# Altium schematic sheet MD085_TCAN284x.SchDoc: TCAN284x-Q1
size 431 x 279 mm; Date: Not shown in title block; ApprovedBy: Not shown in title block; CheckedBy: Not shown in title block; Author: Not shown in title block; CompanyName: Not shown in title block; DrawnBy: Keerthi Kumanan; Engineer: Not shown in title block; Organization: Not shown in title block; Address1: Not shown in title block; Address2: Not shown in title block; Address3: Not shown in title block; Address4: Not shown in title block; DocumentNumber: 1; Revision: Use project parameter SCH_Rev; SheetNumber: 5; SheetTotal: 1; PageSetup: Record=PageOptions¦CenterHorizontal=True¦CenterVertical=True¦PrintScale=1.00¦XCorrection=1.00¦YCorrection=1.00¦PrintKind=0¦BorderSize=5000000¦LeftOffset=0¦BottomOffset=0¦Orientation=2¦PaperLength=1000¦PaperWidth=1000¦Scale=100¦PaperSource=15¦PrintQuality=600¦MediaType=1¦DitherType=10¦PaperKind=Letter¦PrintScaleMode=1
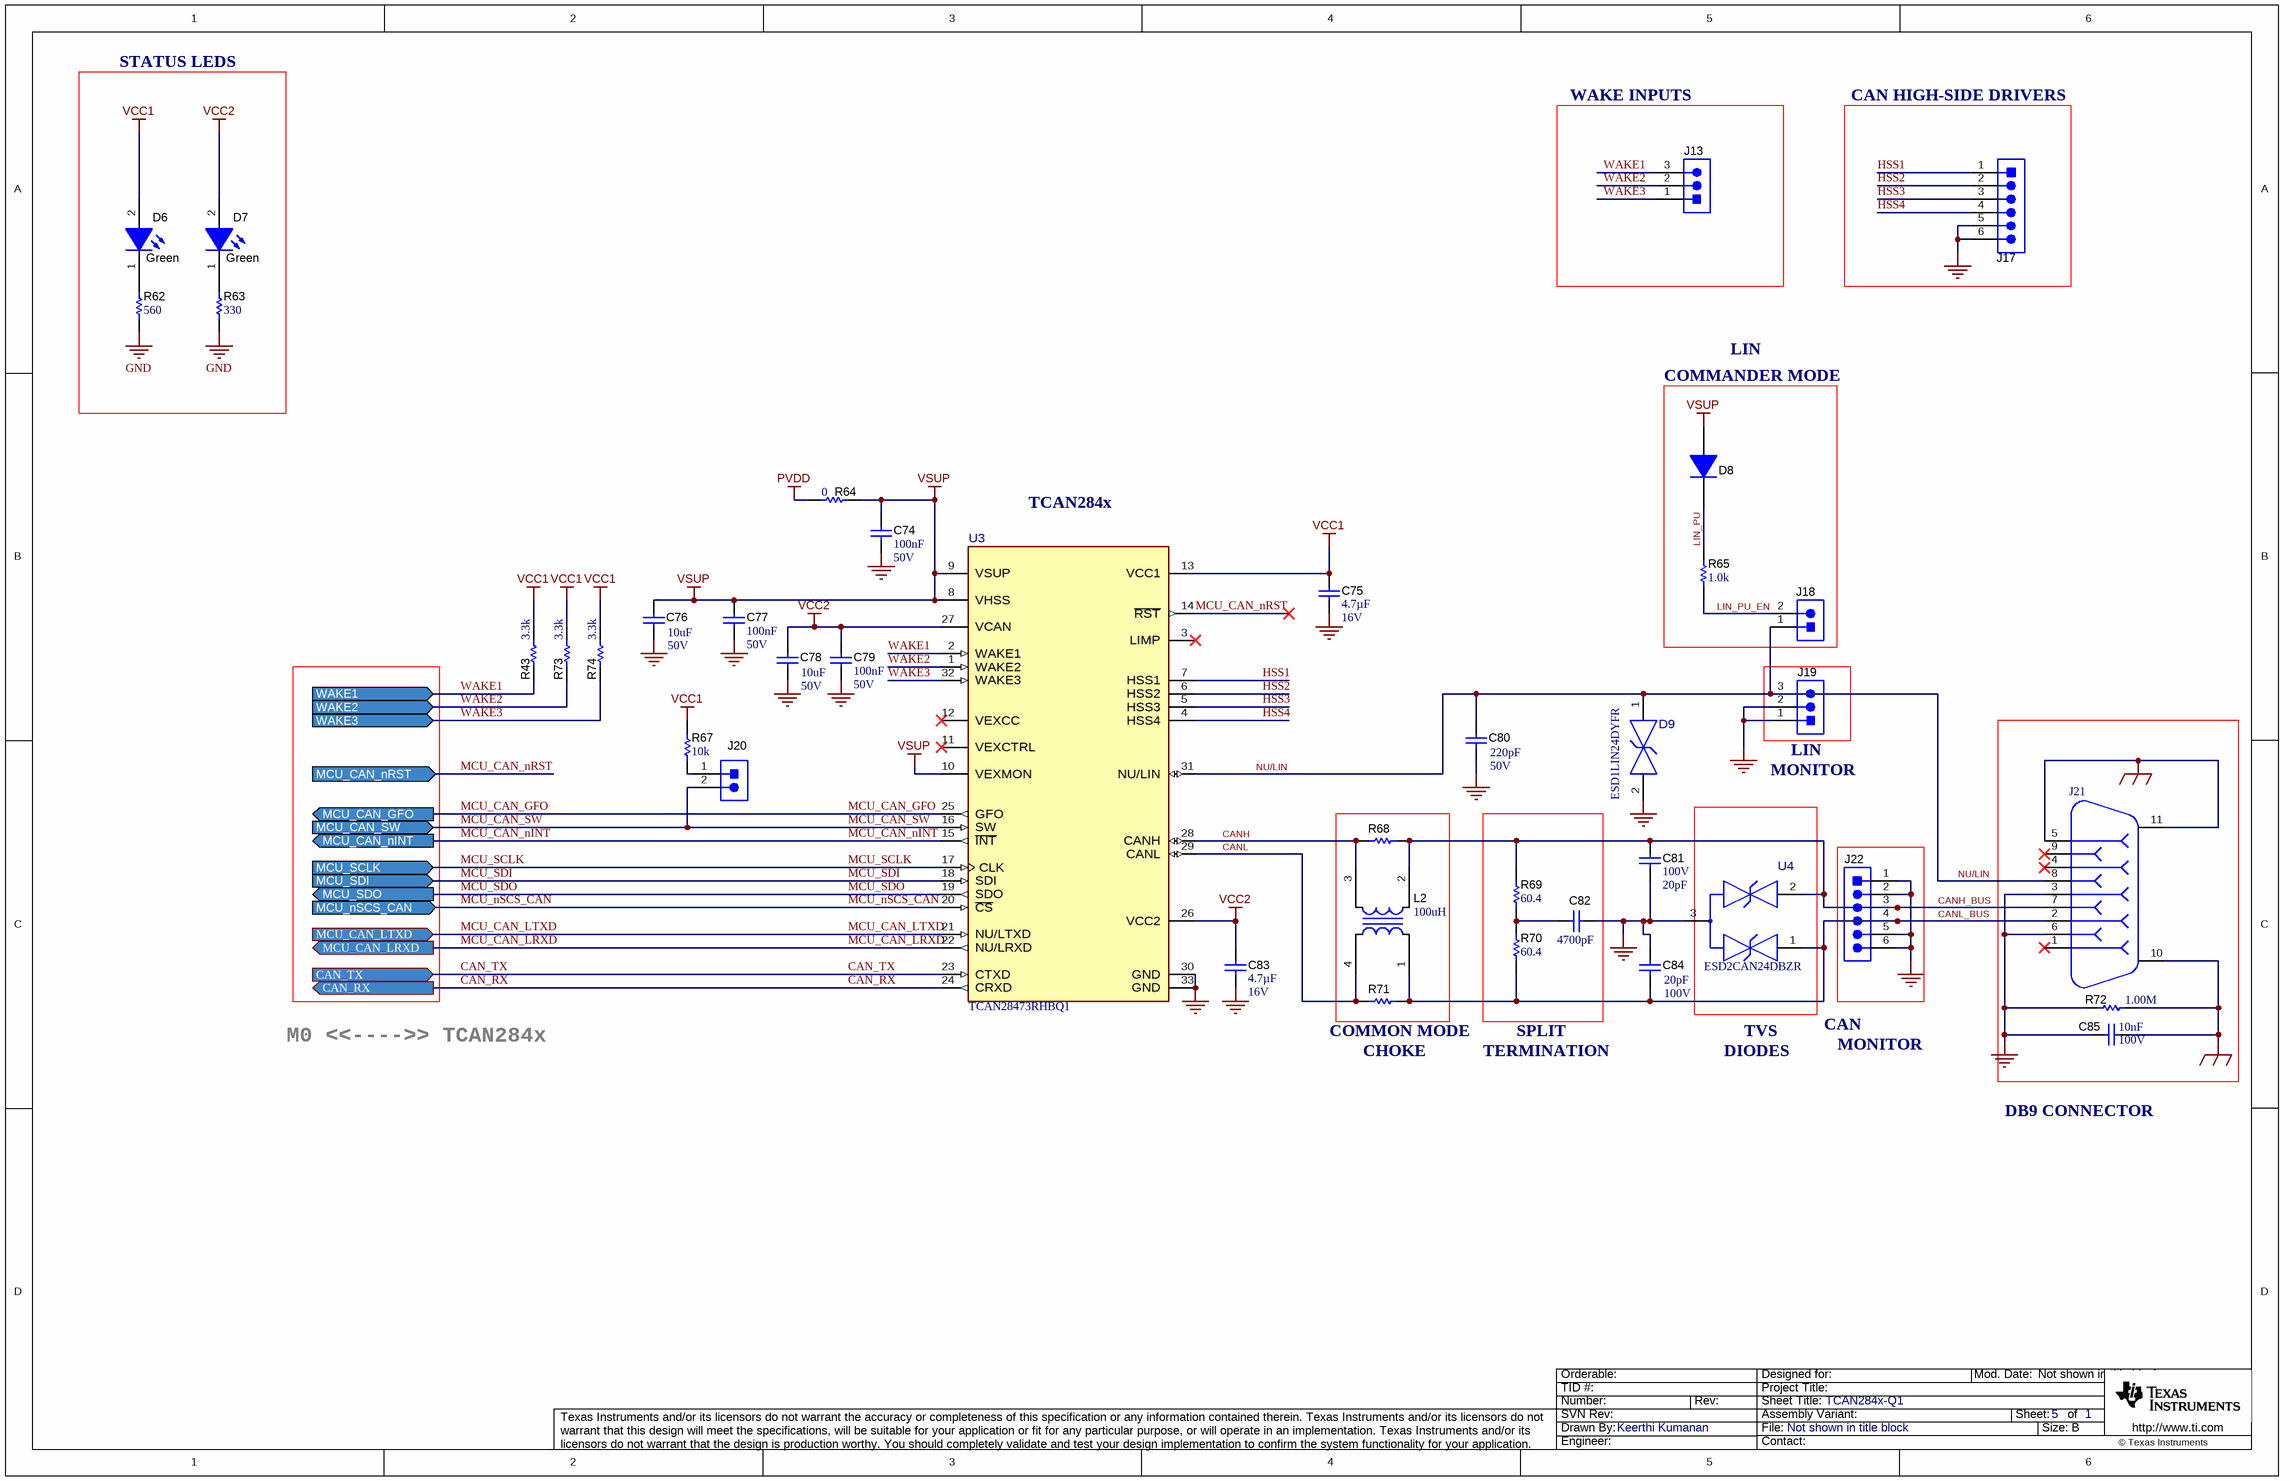
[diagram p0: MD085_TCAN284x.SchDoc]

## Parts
C74  Cap_F: 100nF  VDC_V: 50V  [0603S]  (hidden comment: C1608X7R1H104K080AA)
C75  Cap_F: 4.7µF  VDC_V: 16V  [0805L]  (hidden comment: CGA4J3X7R1C475K125AE)
C76  VDC_V: 50V  ValueDisplayed: 10uF  [1206_180]  (hidden comment: CL31B106KBHNNNE)
C77  Cap_F: 100nF  VDC_V: 50V  [0603S]  (hidden comment: C1608X7R1H104K080AA)
C78  VDC_V: 50V  ValueDisplayed: 10uF  [1206_180]  (hidden comment: CL31B106KBHNNNE)
C79  Cap_F: 100nF  VDC_V: 50V  [0603S]  (hidden comment: C1608X7R1H104K080AA)
C80  Value2: 50V  ValueDisplayed: 220pF  [0603S]  (hidden comment: 06035A221FAT2A)
C81  VDC_V: 100V  ValueDisplayed: 20pF  [0603S]  (hidden comment: GRM1885C2A200JA01D)
C82  ValueDisplayed: 4700pF  [0603S]  (hidden comment: 06031C472KAT2A)
C83  Cap_F: 4.7µF  VDC_V: 16V  [0805L]  (hidden comment: CGA4J3X7R1C475K125AE)
C84  VDC_V: 100V  ValueDisplayed: 20pF  [0603S]  (hidden comment: GRM1885C2A200JA01D)
C85  Cap_F: 10nF  VDC_V: 100V  [0603S]  (hidden comment: C0603X103K1RACTU)
D6  value Green  [WL-SMCW_GREEN]  (hidden comment: 150060VS75000)
D7  value Green  [WL-SMCW_GREEN]  (hidden comment: 150060VS75000)
D8  1N4148W-TP  [SOD-123]  (value not drawn)
D9  ESD1LIN24DYFR  [DYF0002A-MFG]
J13  TSW-103-07-G-S  [TSW-103-07-G-S]  (value not drawn)
J17  TSW-106-07-G-S  [TSW-106-07-G-S]  (value not drawn)
J18  TSW-102-07-G-S  [TSW-102-07-G-S]  (value not drawn)
J19  TSW-103-07-G-S  [TSW-103-07-G-S]  (value not drawn)
J20  TSW-102-07-G-S  [TSW-102-07-G-S]  (value not drawn)
J21  190-009-263R001  [NORCOMP_190-009-263R001]  (value not drawn)
J22  TSW-106-07-G-S  [TSW-106-07-G-S]  (value not drawn)
L2  ValueDisplayed: 100uH  [ACT45B_NoSilk]  (hidden comment: ACT45B-101-2P-TL003)
R43  ValueDisplayed: 3.3k  [0603]  (hidden comment: RC0603JR-073K3L)
R62  ValueDisplayed: 560  [0603]  (hidden comment: RC0603JR-07560RL)
R63  ValueDisplayed: 330  [0603]  (hidden comment: RC0603JR-07330RL)
R64  value 0  [0603]  (hidden comment: Resistor)
R65  ValueDisplayed: 1.0k  [0603]  (hidden comment: RC0603JR-071KL)
R67  ValueDisplayed: 10k  [0603]  (hidden comment: RC0603JR-0710KL)
R68  RC0603JR-070RL  [0603]  (value not drawn)
R69  ValueDisplayed: 60.4  [0603S]  (hidden comment: RC0603FR-0760R4L)
R70  ValueDisplayed: 60.4  [0603S]  (hidden comment: RC0603FR-0760R4L)
R71  RC0603JR-070RL  [0603]  (value not drawn)
R72  ValueDisplayed: 1.00M  [0402S]  (hidden comment: ERJ-2RKF1004X)
R73  ValueDisplayed: 3.3k  [0603]  (hidden comment: RC0603JR-073K3L)
R74  ValueDisplayed: 3.3k  [0603]  (hidden comment: RC0603JR-073K3L)
U3  TCAN28473RHBQ1  [RHB0032U-MFG]
U4  ESD2CAN24DBZR  [DBZ0003A-MFG]

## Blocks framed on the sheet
STATUS LEDS: D6 D7 R62 R63
WAKE INPUTS: J13
CAN HIGH-SIDE DRIVERS: J17
COMMANDER MODE: D8 J18 R65

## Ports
CAN_RX (out), CAN_TX (in), MCU_CAN_GFO (out), MCU_CAN_LRXD (out), MCU_CAN_LTXD (in), MCU_CAN_nINT (out), MCU_CAN_nRST (in), MCU_CAN_SW (in), MCU_nSCS_CAN (in), MCU_SCLK (in), MCU_SDI (in), MCU_SDO (out), WAKE1 (in), WAKE2 (in), WAKE3 (in)

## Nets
GND: C74.2 C75.2 C76.2 C77.2 C78.2 C79.2 C80.2 C81.2 C82.1 C83.2 C84.1 C85.2 D9.2(GND) J17.5 J17.6 J19.1 J19.2 J21.3 J21.6 J22.1 J22.2 J22.5 J22.6 R62.1 R63.1 R72.1 U3.30(GND) U3.33(GND) U4.3(GND)
PVDD: R64.2
SHIELD_GND: C85.1 J21.5 J21.10 J21.11 R72.2
VCC1: C75.1 D6.2(A) R43.2 R67.2 R73.2 R74.2 U3.13(VCC1)
VCC2: C78.1 C79.1 C83.1 D7.2(A) U3.26(VCC2) U3.27(VCAN)
VSUP: C74.1 C76.1 C77.1 D8.2(A) R64.1 U3.8(VHSS) U3.9(VSUP) U3.10(VEXMON)
CAN_RX: U3.24(CRXD) ; port CAN_RX
CAN_TX: U3.23(CTXD) ; port CAN_TX
CANH: L2.3 R68.1 U3.28(CANH)
CANH_BUS: C81.1 J21.7 J22.3 L2.2 R68.2 R69.2 U4.2(2_IO)
CANL: L2.4 R71.1 U3.29(CANL)
CANL_BUS: C84.2 J21.2 J22.4 L2.1 R70.1 R71.2 U4.1(1_IO)
HSS1: J17.1 U3.7(HSS1)
HSS2: J17.2 U3.6(HSS2)
HSS3: J17.3 U3.5(HSS3)
HSS4: J17.4 U3.4(HSS4)
LIN_PU: D8.1(K) R65.1
LIN_PU_EN: J18.2 R65.2
MCU_CAN_GFO: U3.25(GFO) ; port MCU_CAN_GFO
MCU_CAN_LRXD: U3.22(NU/LRXD) ; port MCU_CAN_LRXD
MCU_CAN_LTXD: U3.21(NU/LTXD) ; port MCU_CAN_LTXD
MCU_CAN_nINT: U3.15(~{INT}) ; port MCU_CAN_nINT
MCU_CAN_nRST: U3.14(~{RST}) ; port MCU_CAN_nRST
MCU_CAN_SW: J20.2 U3.16(SW) ; port MCU_CAN_SW
MCU_nSCS_CAN: U3.20(~{CS}) ; port MCU_nSCS_CAN
MCU_SCLK: U3.17(CLK) ; port MCU_SCLK
MCU_SDI: U3.18(SDI) ; port MCU_SDI
MCU_SDO: U3.19(SDO) ; port MCU_SDO
NU/LIN: C80.1 D9.1(IO) J18.1 J19.3 J21.8 U3.31(NU/LIN)
WAKE1: J13.3 R43.1 U3.2(WAKE1) ; port WAKE1
WAKE2: J13.2 R73.1 U3.1(WAKE2) ; port WAKE2
WAKE3: J13.1 R74.1 U3.32(WAKE3) ; port WAKE3
NetC82_2: C82.2 R69.1 R70.2
NetD6_1: D6.1(K) R62.2
NetD7_1: D7.1(K) R63.2
NetJ20_1: J20.1 R67.1

Not connected (* = marked no-connect by the designer): J21 1* 4* 9*; U3 3(LIMP)* 11(VEXCTRL)* 12(VEXCC)*

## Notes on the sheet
- LIN
- TCAN284x
- (near J19) LIN
- (near J19) MONITOR
- CAN
- M0 <<---->> TCAN284x
- (near R71) COMMON MODE
- (near R71) CHOKE
- TERMINATION
- SPLIT
- DIODES
- TVS
- MONITOR
- DB9 CONNECTOR

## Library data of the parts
C74 C77 C79 = CMP-0007044-5: CAP, CERM, 0.1 uF, 50 V, +/- 10%, X7R, 0603; Manufacturer: TDK; TaMin_C: -55°C; ESR_ohm: 29.6m; Polarized: N; SizeAreaWB_mm2: 4.68; Value1: 0.0296 ohm; U/M: EA; Value: 0.1uF; TaMax_C: 125°C; SizeZ_mm: 1; SizeX_mm: 1.6; SizeY_mm: 0.8; Cap_Case: 0603; SizeArea_mm2: 1.28; IRMS_A: 971.99mA; AEC Category: Q200
C75 C83 = CMP-0080701-1: CAP, CERM, 4.7 µF, 16 V,+/- 10%, X7R, AEC-Q200 Grade 1, 0805; Manufacturer: TDK; SizeAreaWB_mm2: 6.75; SizeArea_mm2: 2.5; AEC Qualified: Y; AEC Category: Q200; Value: 4.7uF; TaMax_C: 125°C; SizeZ_mm: 1.45; AEC Grade: 1; Polarized: N; TaMin_C: -55°C; SizeY_mm: 1.25; U/M: EA; SizeX_mm: 2; Cap_Case: 0805
C76 C78 = CMP-0008802-2: CAP, CERM, 10 uF, 50 V, +/- 10%, X7R, 1206; Manufacturer: Samsung; TaMin_C: -55°C; Polarized: N; SizeAreaWB_mm2: 10.92; Value1: Unknown; U/M: EA; Value: 10uF; TaMax_C: 125°C; SizeZ_mm: 1.8; SizeX_mm: 3.2; SizeY_mm: 1.6; Cap_Case: 1206; SizeArea_mm2: 5.12; Cap_F: 10µF; AEC Category: Q200
C80 = CMP-0006776-4: CAP, CERM, 220 pF, 50 V, +/- 1%, C0G/NP0, 0603; Manufacturer: AVX; TaMin_C: -55°C; ESR_ohm: 83m; Polarized: N; SizeAreaWB_mm2: 4.68; Value1: 0.083 ohm; U/M: EA; Value: 220pF; TaMax_C: 125°C; SizeZ_mm: 1; SizeX_mm: 1.6; SizeY_mm: 0.8; Cap_Case: 0603; SizeArea_mm2: 1.28; AEC Category: Q200
C81 C84 = CMP-0007253-4: CAP, CERM, 20 pF, 100 V, +/- 5%, C0G/NP0, 0603; Manufacturer: MuRata; TaMin_C: -55°C; Polarized: N; SizeAreaWB_mm2: 4.68; Value1: Unknown; U/M: EA; Value: 20pF; TaMax_C: 125°C; SizeZ_mm: 1; SizeX_mm: 1.6; SizeY_mm: 0.8; Cap_Case: 0603; SizeArea_mm2: 1.28; AEC Category: Q200
C82 = CMP-0006746-5: CAP, CERM, 4700 pF, 100 V, +/- 10%, X7R, 0603; Manufacturer: AVX; TaMin_C: -55°C; ESR_ohm: 0.136; Polarized: N; SizeAreaWB_mm2: 4.68; Value1: 0.136 ohm; U/M: EA; Value: 4700pF; TaMax_C: 125°C; SizeZ_mm: 1; SizeX_mm: 1.6; SizeY_mm: 0.8; Cap_Case: 0603; Value2: 100V; SizeArea_mm2: 1.28; Cap_F: 4.7nF; AEC Category: Q200
C85 = CMP-0006977-4: CAP, CERM, 0.01 uF, 100 V, +/- 10%, X7R, 0603; Manufacturer: Kemet; TaMin_C: -55°C; Polarized: N; SizeAreaWB_mm2: 4.68; Value1: Unknown; U/M: EA; Value: 0.01uF; TaMax_C: 125°C; SizeZ_mm: 1; SizeX_mm: 1.6; SizeY_mm: 0.8; Cap_Case: 0603; SizeArea_mm2: 1.28; AEC Category: Q200
D6 D7 = CMP-0002894-2: LED, Green, SMD; Manufacturer: Wurth Elektronik; Type: AlInGaP; Value2: 2V; Io_A: 20mA; Value1: W
D8 = CMP-0076974-2: Diode, Switching, 100 V, 0.15 A, SOD-123; Manufacturer: Micro Commercial Components; SizeAreaWB_mm2: 13.095; Vr_V: 100V; SizeArea_mm2: 6.545; TJmax_C: 150°C; AEC Category: Q101; Value: 100V; SizeZ_mm: 1.35; Green_REACh: Incomplete; Io_A: 150mA; Vf_V: 1.25V; SizeY_mm: 1.7; Green_Lifecycle: Not Set; Value1: 0.15A; SizeX_mm: 3.85
D9 = CMP-0098376-1: 24-V, 1-Channel ESD Protection Diode; Manufacturer: Texas Instruments; AEC Qualified: No; SizeZ_mm: 1mm; VRWM: 24V; Ipp: 16A; Ppk: 159.1W; Breakdown Voltage: 25.5V; Cap_F: 2.3pF; Clamping Voltage: 40V; Direction: Bidirectional; Number Of Channels: 1; Standoff Height: 0mm; TaMax_C: +150°C; TaMin_C: -55°C
J13 J19 = CMP-0075407-2: Header, 100mil, 3x1, Gold, TH; Manufacturer: Samtec; Pitch_mm: 2.54; Gender: Male; Cert_CSA: Y; Row_Count: 1; Cert_CULUS: N; Current_A: 6.3A; Green_Lifecycle: Active; Green_REACh: Passed; Voltage_V: 550V
J17 J22 = CMP-0075413-2: Header, 100mil, 6x1, Gold, TH; Manufacturer: Samtec; Pitch_mm: 2.54; Cert_VDE: N; Gender: Male; Cert_CSA: Y; Voltage_V: 550V; Green_REACh: Passed; Current_A: 6.3A; Green_Lifecycle: Active; Row_Count: 1
J18 J20 = CMP-0075405-3: Header, 100mil, 2x1, Gold, TH; Manufacturer: Samtec; Pitch_mm: 2.54; Gender: Male; Cert_CSA: Y; Row_Count: 1; Cert_CULUS: N; Current_A: 6.3A; Green_Lifecycle: Active; Green_REACh: Passed; Voltage_V: 550V
J21 = CMP-0074875-1: Receptacle, D-Sub, 9 Position, R/A, SMT; Manufacturer: NorComp; CNHeader: False; Green_Lifecycle: Not Set; Gender: Female; Green_REACh: Incomplete; Row_Count: 2; ContactFinish: Gold; CT: True
L2 = CMP-0062430-2: Inductor, Ferrite, 100 uH, 0.15 A, 2 ohm, SMD; Manufacturer: TDK; Isat: 0.15A @ % inductance drop; Green_Lifecycle: Active; SizeAreaWB_mm2: 23.1; DCR_ohm: 2; Green_REACh: Passed; Value1: 2 ohm; Value: 100uH; Imax_A: 150mA; SizeZ_mm: 3; SizeX_mm: 4.5; SizeY_mm: 3.2; Value2: 0.15A; SizeArea_mm2: 14.4; Ind_H: 100µH; AEC Category: Q200
R43 R73 R74 = CMP-0025918-5: RES, 3.3 k, 5%, 0.1 W, 0603; Manufacturer: Yageo; Power_W: 100mW; TempCo: 100 ppm/C; Value_Code: 3k30; Value: 3.3k; SizeX_mm: 1.6; SizeY_mm: 0.8; SizeZ_mm: 1; Value2: 0.1W; SizeArea_mm2: 1.28; AEC Qualified: N; VDC_V: 75V; AEC Category: Q200; EIA_Code: E24; SizeAreaWB_mm2: 4.68
R62 = CMP-0025930-5: RES, 560, 5%, 0.1 W, 0603; Manufacturer: Yageo; Power_W: 100mW; TempCo: 100 ppm/C; Value_Code: 560R; Value: 560; EIA_Code: E24; SizeX_mm: 1.6; SizeY_mm: 0.8; SizeZ_mm: 1; Value2: 0.1W; SizeArea_mm2: 1.28; AEC Qualified: N; VDC_V: 75V; AEC Category: Q200; SizeAreaWB_mm2: 4.68
R63 = CMP-0025912-5: RES, 330, 5%, 0.1 W, 0603; Manufacturer: Yageo; Power_W: 100mW; TempCo: 100 ppm/C; Value_Code: 330R; Value: 330; EIA_Code: E24; SizeX_mm: 1.6; SizeY_mm: 0.8; SizeZ_mm: 1; Value2: 0.1W; SizeArea_mm2: 1.28; AEC Qualified: N; VDC_V: 75V; AEC Category: Q200; SizeAreaWB_mm2: 4.68
R64 = CMP-0025885-5: RES, 0, 5%, 0.1 W, 0603; PartNumber: RC0603JR-070RL; Manufacturer: Yageo; Power_W: 100mW; VDC_V: 75V; AEC Qualified: N; SizeZ_mm: 1; AEC Category: Q200; EIA_Code: E24; SizeArea_mm2: 1.28; SizeAreaWB_mm2: 4.68; SizeX_mm: 1.6; SizeY_mm: 0.8; TempCo: 200 ppm/C; Value2: 0.1W; Value_Code: 0000
R65 = CMP-0025899-5: RES, 1.0 k, 5%, 0.1 W, 0603; Manufacturer: Yageo; Power_W: 100mW; TempCo: 100 ppm/C; Value_Code: 1k00; Value: 1.0k; EIA_Code: E24; Res_ohm: 1k; SizeX_mm: 1.6; SizeY_mm: 0.8; SizeZ_mm: 1; Value2: 0.1W; SizeArea_mm2: 1.28; AEC Qualified: N; VDC_V: 75V; AEC Category: Q200; SizeAreaWB_mm2: 4.68
R67 = CMP-0025886-5: RES, 10 k, 5%, 0.1 W, 0603; Manufacturer: Yageo; Value: 10k; SizeY_mm: 0.8; SizeArea_mm2: 1.28; EIA_Code: E24; Power_W: 100mW; SizeX_mm: 1.6; Value2: 0.1W; Value_Code: 10k0; VDC_V: 75V; SizeZ_mm: 1; AEC Qualified: N; AEC Category: Q200; TempCo: 100 ppm/C; SizeAreaWB_mm2: 4.68
R68 R71 = CMP-0025885-5: RES, 0, 5%, 0.1 W, 0603; Manufacturer: Yageo; AEC Qualified: N; Res_ohm: 0; Value: 0; SizeZ_mm: 1; Power_W: 100mW; VDC_V: 75V; AEC Category: Q200; EIA_Code: E24; SizeArea_mm2: 1.28; SizeAreaWB_mm2: 4.68; SizeX_mm: 1.6; SizeY_mm: 0.8; TempCo: 200 ppm/C; Value2: 0.1W; Value_Code: 0000
R69 R70 = CMP-0023213-5: RES, 60.4, 1%, 0.1 W, 0603; Manufacturer: Yageo; Power_W: 100mW; TempCo: 100 ppm/C; Value_Code: 60R4; Value: 60.4; EIA_Code: E96; SizeX_mm: 1.6; SizeY_mm: 0.8; SizeZ_mm: 1; Value2: 0.1W; SizeArea_mm2: 1.28; AEC Qualified: N; VDC_V: 75V; AEC Category: Q200; SizeAreaWB_mm2: 4.68
R72 = CMP-0026660-1: RES, 1.00 M, 1%, 0.1 W, 0402; Manufacturer: Panasonic; Power_W: 100mW; TempCo: 100 ppm/C; Value_Code: 1M00; U/M: EA; Value: 1.00Meg; EIA_Code: E96; Res_ohm: 1M; SizeX_mm: 1; SizeY_mm: 0.5; SizeZ_mm: 0.6; Value2: 0.1W; VDC_V: 50V; AEC Category: Q200
U3 = CMP-0093295-1: CAN FD and LIN System Basis Chip (SBC) with Integrated Watchdog, Selective Wake and Advanced CAN Bus Fault Diagnostics; Manufacturer: Texas Instruments; TJmax_C: +150°C; Min Supply Voltage: 4.5V; Interface: SPI,CAN,LIN; Standoff Height: 0mm; AEC Grade: Grade 1; SizeZ_mm: 1mm; Max Supply Voltage: 28V; AEC Qualified: Yes
U4 = CMP-0093261-1: 24-V, 2-Channel ESD Protection Diode for In-Vehicle Networks; Manufacturer: Texas Instruments; Cap_F: 3pF; Breakdown Voltage: 25.5V; Clamping Voltage: 32V; TaMax_C: +150°C; Direction: Bidirectional; TaMin_C: -55°C; Ipp: 3.5A; VRWM: 24V; Standoff Height: 0.01mm; SizeZ_mm: 1.12mm; Ppk: 147W; AEC Qualified: No; Number Of Channels: 2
